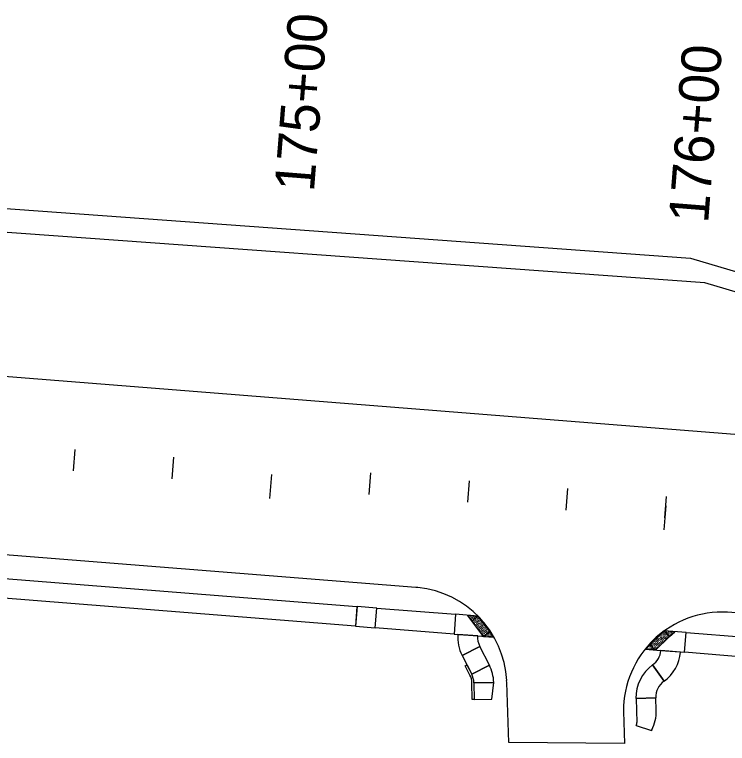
# Model space of a CAD drawing. Extents: x 20499216 to 20505321, y 7953487 to 7960535.
# Drawn here: x 20501145.7 to 20501326, y 7953875.3 to 7954059.7 of the extents above; entities that cross this region are included whole.
import ezdxf

# ---------------------------------------------------------------- set-up
doc = ezdxf.new("R2010")
doc.units = 0
for name, color, linetype in [('Drainage', 7, 'Continuous'), ('EXT_CU', 7, 'Continuous'), ('EXT_RR', 7, 'Continuous'), ('EXT_SNP', 7, 'Continuous'), ('NamedBoundary', 7, 'Continuous'), ('Roadways', 7, 'Continuous'), ('Safety', 7, 'Continuous')]:
    doc.layers.add(name, color=color, linetype=linetype)

msp = doc.modelspace()

# ---------------------------------------------------------------- linework, layer by layer
at = {"layer": 'Drainage'}
for p, q in [((20501262.8, 7953902.55), (20501257.81, 7953902.94)), ((20501258.87, 7953897.61), (20501263.33, 7953899.88)), ((20501314.1, 7953898.47), (20501309.12, 7953898.87)), ((20501265.76, 7953895.12), (20501261.3, 7953892.85)), ((20501309.93, 7953891.12), (20501307.03, 7953895.19)), ((20501307.03, 7953895.19), (20501309.93, 7953891.12)), ((20501261.85, 7953890.68), (20501266.85, 7953890.77)), ((20501302.84, 7953886.71), (20501307.84, 7953886.88)), ((20501302.91, 7953879.9), (20501306.78, 7953878.61)), ((20501306.86, 7953878.77), (20501306.86, 7953878.77))]:
    msp.add_line(p, q, dxfattribs=at)
for points in [[(20501256.82, 7953903.02), (20501236.88, 7953904.61), (20501237.28, 7953909.59), (20501257.21, 7953908.01)], [(20501330.05, 7953897.2), (20501315.1, 7953898.39), (20501315.5, 7953903.38), (20501330.45, 7953902.19)], [(20501258.87, 7953897.61), (20501261.3, 7953892.85), (20501265.76, 7953895.12), (20501263.33, 7953899.88)], [(20501261.85, 7953890.68), (20501261.93, 7953886.46), (20501266.35, 7953886.51), (20501266.85, 7953890.77)]]:
    msp.add_lwpolyline(points, close=True, dxfattribs=at)
msp.add_lwpolyline([(20501307.94, 7953883.64), (20501307.84, 7953886.88), (20501302.84, 7953886.71), (20501303.04, 7953880.67)], dxfattribs=at)
for centre, radius, start, end in [((20501267.78, 7953902.15), 10, 175.4564, 207.0356), ((20501267.78, 7953902.15), 5, 175.4564, 207.0356), ((20501304.14, 7953899.26), 5, 305.4398, 355.4564), ((20501304.14, 7953899.26), 10, 305.4398, 355.4564), ((20501256.85, 7953890.58), 10, 1.1255, 27.0356), ((20501312.83, 7953887.04), 10, 125.4398, 181.902), ((20501256.85, 7953890.58), 5, 1.1255, 27.0356), ((20501312.83, 7953887.04), 5, 125.4398, 181.902), ((20501297.95, 7953883.31), 10, 333.0191, 1.902), ((20501301.04, 7953880.61), 2, 339.1831, 1.902), ((20501312.26, 7953876.02), 6.06, 153.0187, 154.7508)]:
    msp.add_arc(centre, radius, start, end, dxfattribs=at)
at = {"layer": 'EXT_CU'}
for p, q in [((20501260.21, 7953907.77), (20501262.87, 7953907.56)), ((20501261.29, 7953906.36), (20501260.21, 7953907.77)), ((20501261.29, 7953906.36), (20501262.87, 7953907.56)), ((20501262.87, 7953907.56), (20501265.88, 7953903.62)), ((20501264.29, 7953902.43), (20501261.29, 7953906.36)), ((20501265.88, 7953903.62), (20501264.29, 7953902.43)), ((20501266.92, 7953902.22), (20501265.88, 7953903.62)), ((20501309.98, 7953903.81), (20501306.39, 7953900.4)), ((20501311.35, 7953902.38), (20501309.98, 7953903.81)), ((20501312.63, 7953903.6), (20501309.98, 7953903.81)), ((20501311.35, 7953902.38), (20501312.63, 7953903.6)), ((20501264.29, 7953902.43), (20501266.92, 7953902.22)), ((20501307.76, 7953898.97), (20501311.35, 7953902.38)), ((20501305.13, 7953899.18), (20501306.39, 7953900.4)), ((20501306.39, 7953900.4), (20501307.76, 7953898.97)), ((20501307.76, 7953898.97), (20501305.13, 7953899.18))]:
    msp.add_line(p, q, dxfattribs=at)
for points in [[(20500965.3, 7953991.78), (20501114.4, 7954012.75), (20501316.65, 7953998.09), (20501476.2, 7953950.79), (20501496.14, 7953949.21), (20501511.25, 7953950.02), (20501604.78, 7953942.58), (20501718.78, 7953932.38), (20501718.33, 7953927.4), (20501604.36, 7953937.6), (20501511.18, 7953945), (20501496.07, 7953944.2), (20501475.28, 7953945.85), (20501320.22, 7953991.82), (20501114.61, 7954006.72), (20500966.14, 7953985.84), (20500961.2, 7953986.29), (20500961.66, 7953991.27)], [(20501029.61, 7953926.09), (20501232.28, 7953909.99), (20501231.88, 7953905), (20501029.72, 7953921.07)]]:
    msp.add_lwpolyline(points, close=True, dxfattribs=at)
for points in [[(20501260.86, 7953892.62), (20501259.64, 7953895), (20501260.09, 7953895.23), (20501261.3, 7953892.85)], [(20501261.85, 7953890.68), (20501261.93, 7953886.46), (20501261.43, 7953886.45), (20501261.35, 7953890.67)]]:
    msp.add_lwpolyline(points, dxfattribs=at)
for centre, radius in [((20501260.59, 7953907.65), 0.0375), ((20501260.59, 7953907.65), 0.0187), ((20501260.84, 7953907.32), 0.0375), ((20501260.84, 7953907.32), 0.0187), ((20501261.07, 7953907.01), 0.0375), ((20501261.07, 7953907.01), 0.0187), ((20501261.15, 7953907.55), 0.0375), ((20501261.15, 7953907.55), 0.0187), ((20501261.39, 7953907.24), 0.0375), ((20501261.39, 7953907.24), 0.0187), ((20501261.62, 7953906.93), 0.0375), ((20501261.62, 7953906.93), 0.0187), ((20501261.7, 7953907.48), 0.0375), ((20501261.7, 7953907.48), 0.0187), ((20501261.94, 7953907.17), 0.0375), ((20501261.94, 7953907.17), 0.0187), ((20501262.25, 7953907.4), 0.0375), ((20501262.25, 7953907.4), 0.0187), ((20501261.31, 7953906.69), 0.0375), ((20501261.31, 7953906.69), 0.0187), ((20501265.55, 7953903.06), 0.0375), ((20501265.86, 7953903.3), 0.0375), ((20501265.86, 7953903.3), 0.0187), ((20501310.57, 7953903.56), 0.0375), ((20501310.57, 7953903.56), 0.0187), ((20501310.84, 7953903.28), 0.0375), ((20501310.84, 7953903.28), 0.0187), ((20501311.12, 7953903.55), 0.0375), ((20501311.12, 7953903.55), 0.0187), ((20501311.39, 7953903.26), 0.0375), ((20501311.39, 7953903.26), 0.0187), ((20501311.67, 7953903.53), 0.0375), ((20501311.67, 7953903.53), 0.0187), ((20501311.94, 7953903.25), 0.0375), ((20501311.94, 7953903.25), 0.0187), ((20501312.24, 7953903.54), 0.0375), ((20501312.24, 7953903.54), 0.0187), ((20501264.93, 7953902.59), 0.0375), ((20501264.93, 7953902.59), 0.0187), ((20501265.24, 7953902.82), 0.0375), ((20501265.24, 7953902.82), 0.0187), ((20501265.48, 7953902.51), 0.0375), ((20501265.48, 7953902.51), 0.0187), ((20501265.55, 7953903.06), 0.0187), ((20501265.79, 7953902.75), 0.0375), ((20501265.79, 7953902.75), 0.0187), ((20501266.02, 7953902.44), 0.0375), ((20501266.02, 7953902.44), 0.0187), ((20501266.1, 7953902.99), 0.0375), ((20501266.1, 7953902.99), 0.0187), ((20501266.34, 7953902.67), 0.0375), ((20501266.34, 7953902.67), 0.0187), ((20501266.57, 7953902.36), 0.0375), ((20501266.57, 7953902.36), 0.0187), ((20501311.11, 7953902.99), 0.0375), ((20501311.11, 7953902.99), 0.0187), ((20501311.38, 7953902.71), 0.0375), ((20501311.38, 7953902.71), 0.0187), ((20501311.66, 7953902.98), 0.0375), ((20501311.66, 7953902.98), 0.0187), ((20501305.78, 7953899.53), 0.0375), ((20501305.78, 7953899.53), 0.0187), ((20501306.07, 7953899.8), 0.0375), ((20501306.07, 7953899.8), 0.0187), ((20501306.34, 7953899.52), 0.0375), ((20501306.35, 7953900.08), 0.0375), ((20501306.34, 7953899.52), 0.0187), ((20501306.35, 7953900.08), 0.0187), ((20501306.62, 7953899.79), 0.0375), ((20501306.62, 7953899.79), 0.0187), ((20501306.89, 7953899.51), 0.0375), ((20501306.89, 7953899.51), 0.0187), ((20501305.5, 7953899.26), 0.0375), ((20501305.5, 7953899.26), 0.0187), ((20501306.05, 7953899.25), 0.0375), ((20501306.05, 7953899.25), 0.0187), ((20501306.61, 7953899.24), 0.0375), ((20501306.61, 7953899.24), 0.0187), ((20501307.16, 7953899.23), 0.0375), ((20501307.16, 7953899.23), 0.0187)]:
    msp.add_circle(centre, radius, dxfattribs=at)
for radius in [4.5, 5]:
    msp.add_arc((20501256.85, 7953890.58), radius, 1.1255, 27.0356, dxfattribs=at)
for centre, major_axis in [((20501262.17, 7953906.85), (0.0371, -0.0034)), ((20501262.17, 7953906.85), (0.0186, -0.0017)), ((20501262.48, 7953907.09), (0.0371, -0.0034)), ((20501262.48, 7953907.09), (0.0186, -0.0017)), ((20501262.71, 7953906.78), (0.0371, -0.0034)), ((20501262.71, 7953906.78), (0.0186, -0.0017)), ((20501262.79, 7953907.32), (0.0371, -0.0034)), ((20501262.79, 7953907.32), (0.0186, -0.0017)), ((20501263.02, 7953907.01), (0.0371, -0.0034)), ((20501263.02, 7953907.01), (0.0186, -0.0017)), ((20501261.55, 7953906.39), (0.0371, -0.0034)), ((20501261.55, 7953906.39), (0.0186, -0.0017)), ((20501261.78, 7953906.08), (0.0371, -0.0034)), ((20501261.78, 7953906.08), (0.0186, -0.0017)), ((20501261.86, 7953906.62), (0.0371, -0.0034)), ((20501261.86, 7953906.62), (0.0186, -0.0017)), ((20501262.02, 7953905.77), (0.0371, -0.0034)), ((20501262.02, 7953905.77), (0.0186, -0.0017)), ((20501262.09, 7953906.31), (0.0371, -0.0034)), ((20501262.09, 7953906.31), (0.0186, -0.0017)), ((20501262.25, 7953905.46), (0.0371, -0.0034)), ((20501262.25, 7953905.46), (0.0186, -0.0017)), ((20501262.33, 7953906), (0.0371, -0.0034)), ((20501262.33, 7953906), (0.0186, -0.0017)), ((20501262.4, 7953906.54), (0.0371, -0.0034)), ((20501262.4, 7953906.54), (0.0186, -0.0017)), ((20501262.49, 7953905.15), (0.0371, -0.0034)), ((20501262.49, 7953905.15), (0.0186, -0.0017)), ((20501262.56, 7953905.69), (0.0371, -0.0034)), ((20501262.56, 7953905.69), (0.0186, -0.0017)), ((20501262.64, 7953906.24), (0.0371, -0.0034)), ((20501262.64, 7953906.24), (0.0186, -0.0017)), ((20501262.8, 7953905.39), (0.0371, -0.0034)), ((20501262.8, 7953905.39), (0.0186, -0.0017)), ((20501262.87, 7953905.93), (0.0371, -0.0034)), ((20501262.87, 7953905.93), (0.0186, -0.0017)), ((20501262.95, 7953906.47), (0.0371, -0.0034)), ((20501262.95, 7953906.47), (0.0186, -0.0017)), ((20501263.04, 7953905.08), (0.0371, -0.0034)), ((20501263.04, 7953905.08), (0.0186, -0.0017)), ((20501263.11, 7953905.62), (0.0371, -0.0034)), ((20501263.11, 7953905.62), (0.0186, -0.0017)), ((20501263.18, 7953906.16), (0.0371, -0.0034)), ((20501263.18, 7953906.16), (0.0186, -0.0017)), ((20501263.26, 7953906.7), (0.0371, -0.0034)), ((20501263.26, 7953906.7), (0.0186, -0.0017)), ((20501263.35, 7953905.31), (0.0371, -0.0034)), ((20501263.35, 7953905.31), (0.0186, -0.0017)), ((20501263.42, 7953905.85), (0.0371, -0.0034)), ((20501263.42, 7953905.85), (0.0186, -0.0017)), ((20501263.49, 7953906.4), (0.0371, -0.0034)), ((20501263.49, 7953906.4), (0.0186, -0.0017)), ((20501263.58, 7953905), (0.0371, -0.0034)), ((20501263.58, 7953905), (0.0186, -0.0017)), ((20501263.65, 7953905.55), (0.0371, -0.0034)), ((20501263.65, 7953905.55), (0.0186, -0.0017)), ((20501263.73, 7953906.09), (0.0371, -0.0034)), ((20501263.73, 7953906.09), (0.0186, -0.0017)), ((20501263.89, 7953905.24), (0.0371, -0.0034)), ((20501263.89, 7953905.24), (0.0186, -0.0017)), ((20501263.96, 7953905.78), (0.0371, -0.0034)), ((20501263.96, 7953905.78), (0.0186, -0.0017)), ((20501264.13, 7953904.93), (0.0371, -0.0034)), ((20501264.13, 7953904.93), (0.0186, -0.0017)), ((20501264.2, 7953905.47), (0.0371, -0.0034)), ((20501264.2, 7953905.47), (0.0186, -0.0017)), ((20501264.44, 7953905.16), (0.0371, -0.0034)), ((20501264.44, 7953905.16), (0.0186, -0.0017)), ((20501262.73, 7953904.84), (0.0371, -0.0034)), ((20501262.73, 7953904.84), (0.0186, -0.0017)), ((20501262.96, 7953904.54), (0.0371, -0.0034)), ((20501262.96, 7953904.54), (0.0186, -0.0017)), ((20501263.2, 7953904.23), (0.0371, -0.0034)), ((20501263.2, 7953904.23), (0.0186, -0.0017)), ((20501263.27, 7953904.77), (0.0371, -0.0034)), ((20501263.27, 7953904.77), (0.0186, -0.0017)), ((20501263.43, 7953903.92), (0.0371, -0.0034)), ((20501263.43, 7953903.92), (0.0186, -0.0017)), ((20501263.51, 7953904.46), (0.0371, -0.0034)), ((20501263.51, 7953904.46), (0.0186, -0.0017)), ((20501263.67, 7953903.61), (0.0371, -0.0034)), ((20501263.67, 7953903.61), (0.0186, -0.0017)), ((20501263.74, 7953904.15), (0.0371, -0.0034)), ((20501263.74, 7953904.15), (0.0186, -0.0017)), ((20501263.82, 7953904.7), (0.0371, -0.0034)), ((20501263.82, 7953904.7), (0.0186, -0.0017)), ((20501263.92, 7953903.29), (0.0371, -0.0034)), ((20501263.92, 7953903.29), (0.0186, -0.0017)), ((20501263.98, 7953903.85), (0.0371, -0.0034)), ((20501263.98, 7953903.85), (0.0186, -0.0017)), ((20501264.05, 7953904.39), (0.0371, -0.0034)), ((20501264.05, 7953904.39), (0.0186, -0.0017)), ((20501264.23, 7953903.52), (0.0371, -0.0034)), ((20501264.23, 7953903.52), (0.0186, -0.0017)), ((20501264.29, 7953904.08), (0.0371, -0.0034)), ((20501264.29, 7953904.08), (0.0186, -0.0017)), ((20501264.36, 7953904.62), (0.0371, -0.0034)), ((20501264.36, 7953904.62), (0.0186, -0.0017)), ((20501264.46, 7953903.21), (0.0371, -0.0034)), ((20501264.46, 7953903.21), (0.0186, -0.0017)), ((20501264.54, 7953903.75), (0.0371, -0.0034)), ((20501264.54, 7953903.75), (0.0186, -0.0017)), ((20501264.6, 7953904.31), (0.0371, -0.0034)), ((20501264.6, 7953904.31), (0.0186, -0.0017)), ((20501264.67, 7953904.85), (0.0371, -0.0034)), ((20501264.67, 7953904.85), (0.0186, -0.0017)), ((20501264.77, 7953903.45), (0.0371, -0.0034)), ((20501264.77, 7953903.45), (0.0186, -0.0017)), ((20501264.85, 7953903.99), (0.0371, -0.0034)), ((20501264.85, 7953903.99), (0.0186, -0.0017)), ((20501264.91, 7953904.55), (0.0371, -0.0034)), ((20501264.91, 7953904.55), (0.0186, -0.0017)), ((20501265.01, 7953903.14), (0.0371, -0.0034)), ((20501265.01, 7953903.14), (0.0186, -0.0017)), ((20501265.08, 7953903.68), (0.0371, -0.0034)), ((20501265.08, 7953903.68), (0.0186, -0.0017)), ((20501265.16, 7953904.22), (0.0371, -0.0034)), ((20501265.16, 7953904.22), (0.0186, -0.0017)), ((20501265.32, 7953903.37), (0.0371, -0.0034)), ((20501265.32, 7953903.37), (0.0186, -0.0017)), ((20501265.39, 7953903.91), (0.0371, -0.0034)), ((20501265.39, 7953903.91), (0.0186, -0.0017)), ((20501265.63, 7953903.61), (0.0371, -0.0034)), ((20501265.63, 7953903.61), (0.0186, -0.0017)), ((20501309.74, 7953903.3), (0.0372, -0.0025)), ((20501309.74, 7953903.3), (0.0186, -0.0013)), ((20501310.02, 7953903.56), (0.0372, -0.0025)), ((20501310.02, 7953903.56), (0.0186, -0.0013)), ((20501310.29, 7953903.28), (0.0372, -0.0025)), ((20501310.29, 7953903.28), (0.0186, -0.0013)), ((20501264.15, 7953902.98), (0.0371, -0.0034)), ((20501264.15, 7953902.98), (0.0186, -0.0017)), ((20501264.39, 7953902.67), (0.0371, -0.0034)), ((20501264.39, 7953902.67), (0.0186, -0.0017)), ((20501264.7, 7953902.9), (0.0371, -0.0034)), ((20501264.7, 7953902.9), (0.0186, -0.0017)), ((20501307.77, 7953901.43), (0.0372, -0.0025)), ((20501307.77, 7953901.43), (0.0186, -0.0013)), ((20501308.05, 7953901.69), (0.0372, -0.0025)), ((20501308.05, 7953901.69), (0.0186, -0.0013)), ((20501308.32, 7953901.41), (0.0372, -0.0025)), ((20501308.33, 7953901.96), (0.0372, -0.0025)), ((20501308.32, 7953901.41), (0.0186, -0.0013)), ((20501308.33, 7953901.96), (0.0186, -0.0013)), ((20501308.6, 7953901.68), (0.0372, -0.0025)), ((20501308.61, 7953902.23), (0.0372, -0.0025)), ((20501308.6, 7953901.68), (0.0186, -0.0013)), ((20501308.61, 7953902.23), (0.0186, -0.0013)), ((20501308.87, 7953901.4), (0.0372, -0.0025)), ((20501308.88, 7953901.95), (0.0372, -0.0025)), ((20501308.87, 7953901.4), (0.0186, -0.0013)), ((20501308.9, 7953902.49), (0.0372, -0.0025)), ((20501308.88, 7953901.95), (0.0186, -0.0013)), ((20501308.9, 7953902.49), (0.0186, -0.0013)), ((20501309.15, 7953901.67), (0.0372, -0.0025)), ((20501309.16, 7953902.21), (0.0372, -0.0025)), ((20501309.15, 7953901.67), (0.0186, -0.0013)), ((20501309.18, 7953902.76), (0.0372, -0.0025)), ((20501309.16, 7953902.21), (0.0186, -0.0013)), ((20501309.18, 7953902.76), (0.0186, -0.0013)), ((20501309.42, 7953901.39), (0.0372, -0.0025)), ((20501309.43, 7953901.93), (0.0372, -0.0025)), ((20501309.42, 7953901.39), (0.0186, -0.0013)), ((20501309.45, 7953902.48), (0.0372, -0.0025)), ((20501309.43, 7953901.93), (0.0186, -0.0013)), ((20501309.46, 7953903.03), (0.0372, -0.0025)), ((20501309.45, 7953902.48), (0.0186, -0.0013)), ((20501309.46, 7953903.03), (0.0186, -0.0013)), ((20501309.7, 7953901.65), (0.0372, -0.0025)), ((20501309.72, 7953902.2), (0.0372, -0.0025)), ((20501309.7, 7953901.65), (0.0186, -0.0013)), ((20501309.73, 7953902.75), (0.0372, -0.0025)), ((20501309.72, 7953902.2), (0.0186, -0.0013)), ((20501309.73, 7953902.75), (0.0186, -0.0013)), ((20501309.97, 7953901.37), (0.0372, -0.0025)), ((20501309.98, 7953901.92), (0.0372, -0.0025)), ((20501309.97, 7953901.37), (0.0186, -0.0013)), ((20501310, 7953902.47), (0.0372, -0.0025)), ((20501310.01, 7953903.02), (0.0372, -0.0025)), ((20501309.98, 7953901.92), (0.0186, -0.0013)), ((20501310, 7953902.47), (0.0186, -0.0013)), ((20501310.01, 7953903.02), (0.0186, -0.0013)), ((20501310.25, 7953901.64), (0.0372, -0.0025)), ((20501310.27, 7953902.19), (0.0372, -0.0025)), ((20501310.25, 7953901.64), (0.0186, -0.0013)), ((20501310.28, 7953902.74), (0.0372, -0.0025)), ((20501310.27, 7953902.19), (0.0186, -0.0013)), ((20501310.28, 7953902.74), (0.0186, -0.0013)), ((20501310.53, 7953901.91), (0.0372, -0.0025)), ((20501310.55, 7953902.46), (0.0372, -0.0025)), ((20501310.56, 7953903), (0.0372, -0.0025)), ((20501310.53, 7953901.91), (0.0186, -0.0013)), ((20501310.55, 7953902.46), (0.0186, -0.0013)), ((20501310.56, 7953903), (0.0186, -0.0013)), ((20501310.82, 7953902.18), (0.0372, -0.0025)), ((20501310.83, 7953902.72), (0.0372, -0.0025)), ((20501310.82, 7953902.18), (0.0186, -0.0013)), ((20501310.83, 7953902.72), (0.0186, -0.0013)), ((20501311.1, 7953902.44), (0.0372, -0.0025)), ((20501311.1, 7953902.44), (0.0186, -0.0013)), ((20501306.63, 7953900.34), (0.0372, -0.0025)), ((20501306.63, 7953900.34), (0.0186, -0.0013)), ((20501306.9, 7953900.06), (0.0372, -0.0025)), ((20501306.91, 7953900.61), (0.0372, -0.0025)), ((20501306.9, 7953900.06), (0.0186, -0.0013)), ((20501306.91, 7953900.61), (0.0186, -0.0013)), ((20501307.17, 7953899.78), (0.0372, -0.0025)), ((20501307.18, 7953900.33), (0.0372, -0.0025)), ((20501307.19, 7953900.88), (0.0372, -0.0025)), ((20501307.17, 7953899.78), (0.0186, -0.0013)), ((20501307.18, 7953900.33), (0.0186, -0.0013)), ((20501307.19, 7953900.88), (0.0186, -0.0013)), ((20501307.44, 7953899.5), (0.0372, -0.0025)), ((20501307.45, 7953900.05), (0.0372, -0.0025)), ((20501307.46, 7953900.6), (0.0372, -0.0025)), ((20501307.44, 7953899.5), (0.0186, -0.0013)), ((20501307.45, 7953900.05), (0.0186, -0.0013)), ((20501307.46, 7953900.6), (0.0186, -0.0013)), ((20501307.49, 7953901.16), (0.0372, -0.0025)), ((20501307.49, 7953901.16), (0.0186, -0.0013)), ((20501307.72, 7953899.77), (0.0372, -0.0025)), ((20501307.73, 7953900.32), (0.0372, -0.0025)), ((20501307.72, 7953899.77), (0.0186, -0.0013)), ((20501307.73, 7953900.32), (0.0186, -0.0013)), ((20501307.76, 7953900.88), (0.0372, -0.0025)), ((20501307.76, 7953900.88), (0.0186, -0.0013)), ((20501307.99, 7953899.49), (0.0372, -0.0025)), ((20501308, 7953900.04), (0.0372, -0.0025)), ((20501307.99, 7953899.49), (0.0186, -0.0013)), ((20501308, 7953900.04), (0.0186, -0.0013)), ((20501308.03, 7953900.6), (0.0372, -0.0025)), ((20501308.04, 7953901.15), (0.0372, -0.0025)), ((20501308.03, 7953900.6), (0.0186, -0.0013)), ((20501308.04, 7953901.15), (0.0186, -0.0013)), ((20501308.27, 7953899.76), (0.0372, -0.0025)), ((20501308.27, 7953899.76), (0.0186, -0.0013)), ((20501308.3, 7953900.32), (0.0372, -0.0025)), ((20501308.31, 7953900.87), (0.0372, -0.0025)), ((20501308.3, 7953900.32), (0.0186, -0.0013)), ((20501308.31, 7953900.87), (0.0186, -0.0013)), ((20501308.57, 7953900.04), (0.0372, -0.0025)), ((20501308.58, 7953900.59), (0.0372, -0.0025)), ((20501308.59, 7953901.13), (0.0372, -0.0025)), ((20501308.57, 7953900.04), (0.0186, -0.0013)), ((20501308.58, 7953900.59), (0.0186, -0.0013)), ((20501308.59, 7953901.13), (0.0186, -0.0013)), ((20501308.85, 7953900.31), (0.0372, -0.0025)), ((20501308.86, 7953900.85), (0.0372, -0.0025)), ((20501308.85, 7953900.31), (0.0186, -0.0013)), ((20501308.86, 7953900.85), (0.0186, -0.0013)), ((20501309.13, 7953900.57), (0.0372, -0.0025)), ((20501309.14, 7953901.12), (0.0372, -0.0025)), ((20501309.13, 7953900.57), (0.0186, -0.0013)), ((20501309.14, 7953901.12), (0.0186, -0.0013)), ((20501309.41, 7953900.84), (0.0372, -0.0025)), ((20501309.41, 7953900.84), (0.0186, -0.0013)), ((20501309.69, 7953901.11), (0.0372, -0.0025)), ((20501309.69, 7953901.11), (0.0186, -0.0013)), ((20501307.71, 7953899.22), (0.0372, -0.0025)), ((20501307.71, 7953899.22), (0.0186, -0.0013))]:
    msp.add_ellipse(centre, major_axis=major_axis, ratio=0.993785, dxfattribs=at)
at = {"layer": 'EXT_RR'}
for p, q in [((20501160.6, 7953944.27), (20501161.03, 7953949.72)), ((20501185.52, 7953942.29), (20501185.95, 7953947.74)), ((20501235.36, 7953938.33), (20501235.8, 7953943.78)), ((20501210.69, 7953943.36), (20501210.2, 7953937.26)), ((20501260.29, 7953936.35), (20501260.72, 7953941.8)), ((20501285.21, 7953934.37), (20501285.64, 7953939.82)), ((20501310.37, 7953935.44), (20501309.89, 7953929.34))]:
    msp.add_line(p, q, dxfattribs=at)
at = {"layer": 'EXT_SNP'}
for points in [[(20501260.86, 7953892.62), (20501259.64, 7953895), (20501260.09, 7953895.23), (20501261.3, 7953892.85)], [(20501261.85, 7953890.68), (20501261.93, 7953886.46), (20501261.43, 7953886.45), (20501261.35, 7953890.67)]]:
    msp.add_lwpolyline(points, dxfattribs=at)
for radius in [4.5, 5]:
    msp.add_arc((20501256.85, 7953890.58), radius, 1.1255, 27.0356, dxfattribs=at)
at = {"layer": 'NamedBoundary'}
for points in [[(20500911.34, 7953941.51), (20500848.24, 7953946.53), (20500808.56, 7953950.16), (20500808.63, 7953950.91), (20500808.63, 7953950.91), (20500809.17, 7953955.67), (20500809.06, 7953955.68), (20500812.15, 7953989.44), (20500804.8, 7953990.07), (20500805.25, 7953995.63), (20500812.66, 7953994.97), (20500852.08, 7953991.36), (20501603.86, 7953931.62), (20501734.26, 7953919.95)], [(20501247.7, 7953914.78), (20501247.15, 7953914.83), (20501247.15, 7953914.83), (20500991.71, 7953935.12), (20500991.36, 7953935.15)], [(20501715.63, 7953876.43), (20501715.33, 7953876.46), (20501600.07, 7953886.78), (20501325.96, 7953908.56), (20501325.96, 7953908.56)], [(20501299.66, 7953883.46), (20501299.93, 7953875.35), (20501270.66, 7953875.56), (20501270.15, 7953890.74), (20501270.13, 7953891.29), (20501270.13, 7953891.29)]]:
    msp.add_lwpolyline(points, dxfattribs=at)
for centre, start, end in [((20501245.15, 7953889.89), 3.2238, 84.1382), ((20501324.7, 7953883.56), 87.1114, 180.247)]:
    msp.add_arc(centre, 25.03, start, end, dxfattribs=at)
at = {"layer": 'Roadways'}
for points in [[(20501236.87, 7953904.61), (20501236.87, 7953904.61), (20501237.28, 7953909.59), (20501232.29, 7953909.99), (20501232.29, 7953909.99), (20501232.29, 7953909.99), (20501231.88, 7953905)], [(20501262.8, 7953902.55), (20501266.92, 7953902.22), (20501265.77, 7953904.06), (20501264.33, 7953905.95), (20501262.87, 7953907.56), (20501257.21, 7953908.01), (20501256.82, 7953903.02)], [(20501309.98, 7953903.81), (20501307.98, 7953902.2), (20501306.7, 7953900.97), (20501305.14, 7953899.18), (20501309.12, 7953898.87), (20501315.1, 7953898.39), (20501315.5, 7953903.38)]]:
    msp.add_lwpolyline(points, close=True, dxfattribs=at)
at = {"layer": 'Safety'}
for p, q in [((20501210.69, 7953943.36), (20501210.2, 7953937.26)), ((20501310.13, 7953932.39), (20501310.56, 7953937.83))]:
    msp.add_line(p, q, dxfattribs=at)

# ---------------------------------------------------------------- texts
at = {"layer": 'EXT_RR'}
for s, p in [('175+00', (20501221.38, 7954014.68)), ('176+00', (20501321.06, 7954006.76))]:
    msp.add_text(s, height=10.02, rotation=85.4564, dxfattribs=at).set_placement(p)
at = {"layer": 'Safety'}
msp.add_text('175+00', height=10.02, rotation=85.4564, dxfattribs=at).set_placement((20501221.38, 7954014.68))

doc.saveas('drawing.dxf')
